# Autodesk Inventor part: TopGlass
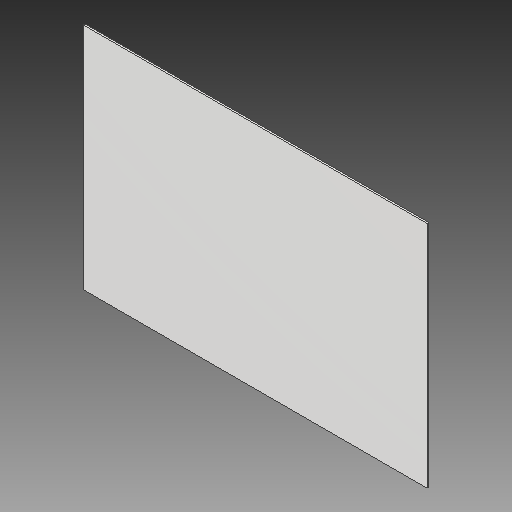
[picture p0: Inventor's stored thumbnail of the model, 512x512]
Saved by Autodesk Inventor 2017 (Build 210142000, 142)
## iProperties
Created: 2017-05
Part Number: TopGlass
Material: Generic
Document SubType Name: Modeling
Designer: Savy
Density: 1 g/cm^3
Appearance: Default
Author: Savy
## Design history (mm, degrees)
feature "SOLID1"
body "Solid1"
